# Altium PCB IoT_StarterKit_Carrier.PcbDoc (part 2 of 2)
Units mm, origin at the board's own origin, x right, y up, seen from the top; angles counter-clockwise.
Board outline 84.71 x 84.24 mm, 4 copper layers (Top, PWR, MID, Bottom), stack 1.612 mm thick; 101 components, 113 nets, 468 pads, 142 vias.
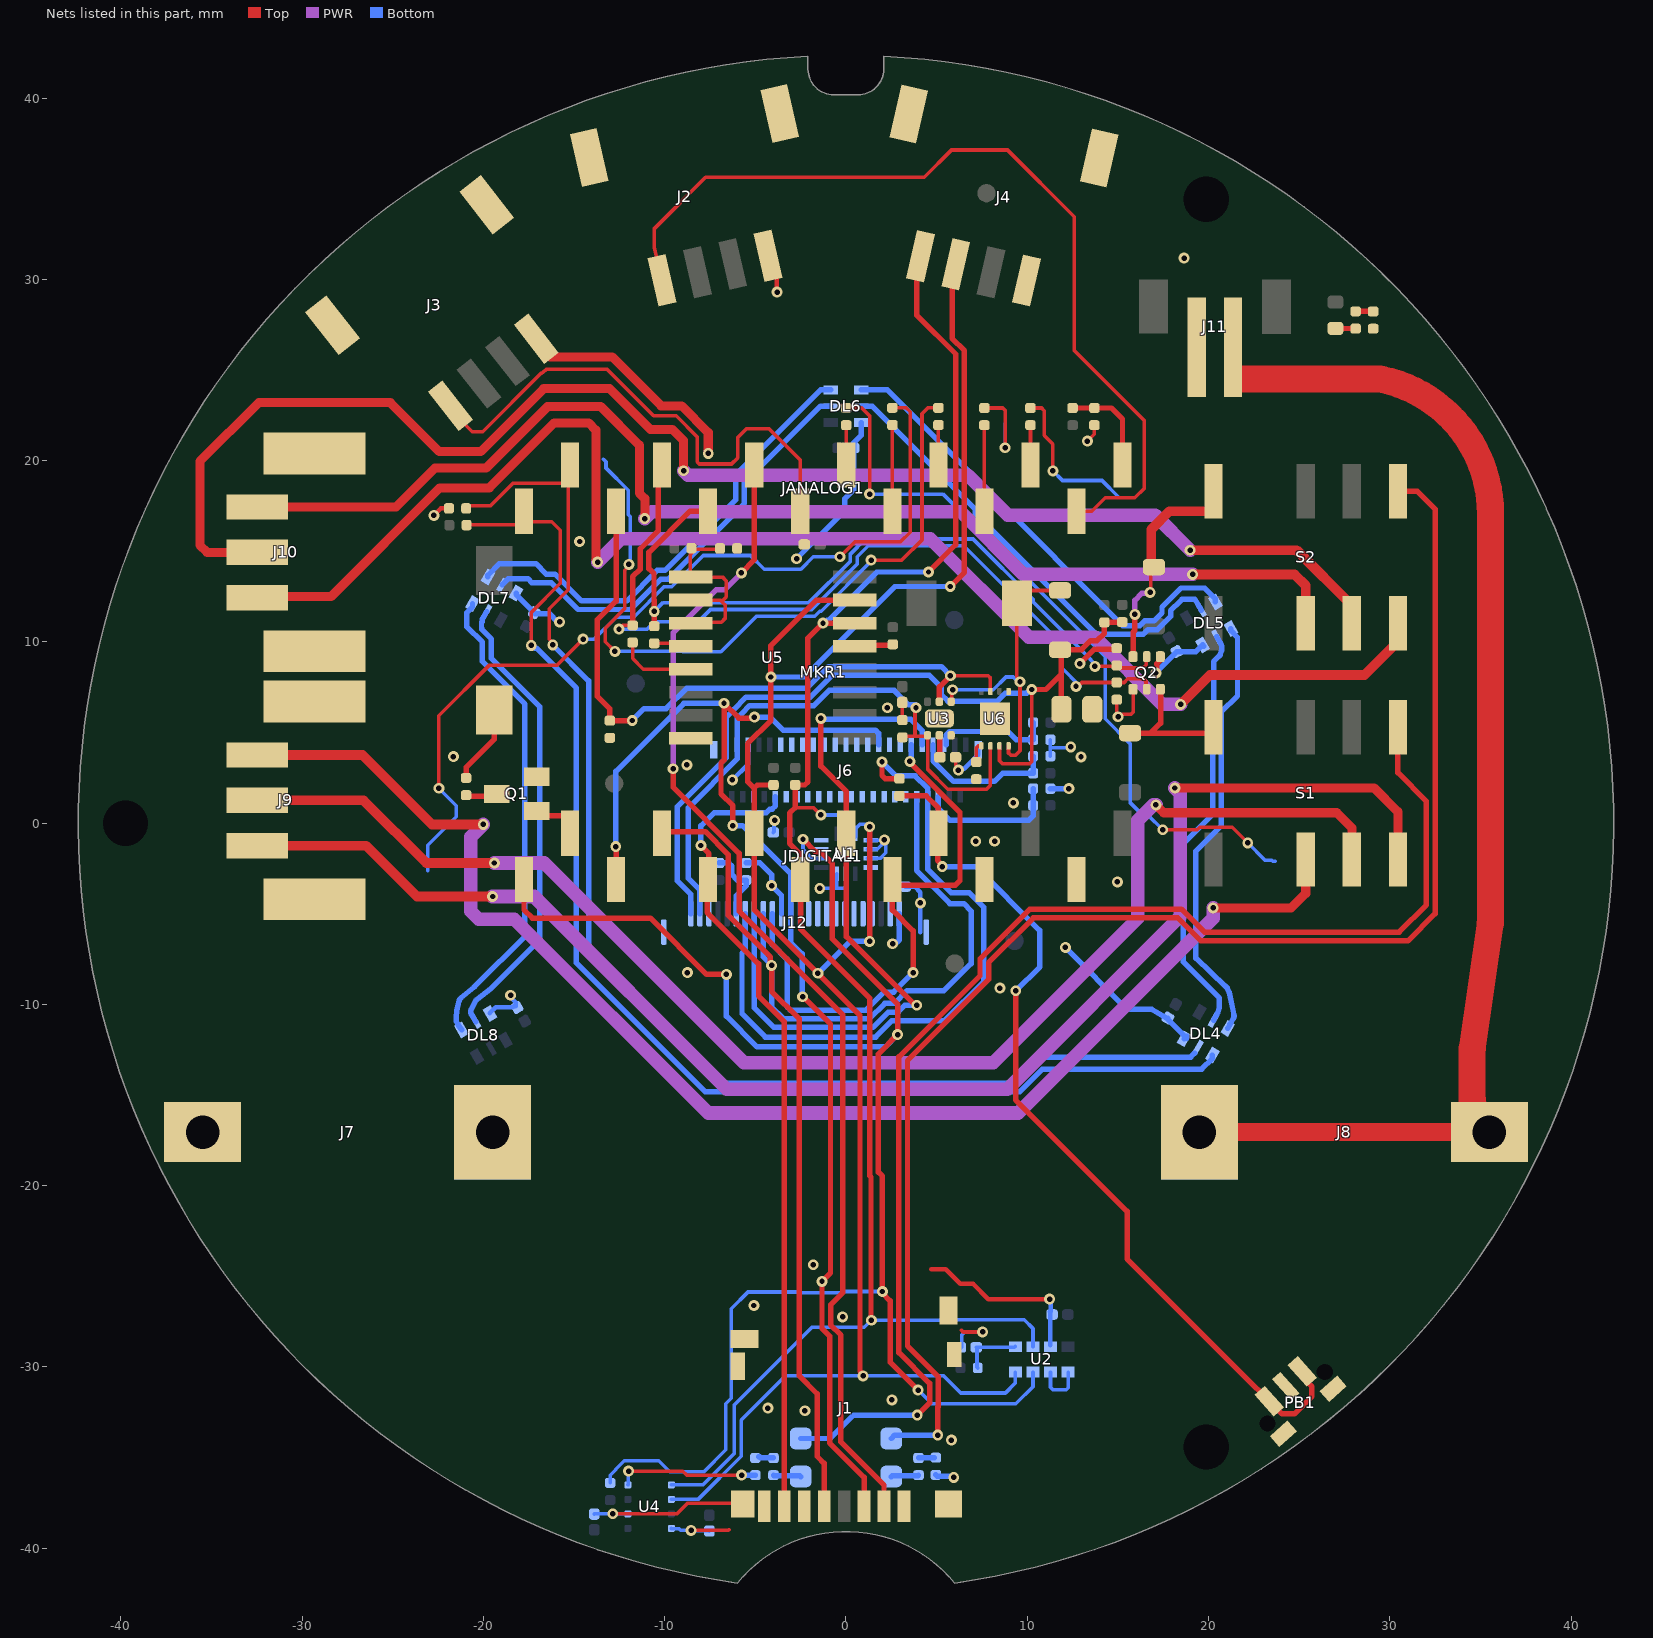
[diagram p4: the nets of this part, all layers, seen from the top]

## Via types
v1: diameter 0.6, hole 0.3, Top to Bottom, tented both sides, 142 vias

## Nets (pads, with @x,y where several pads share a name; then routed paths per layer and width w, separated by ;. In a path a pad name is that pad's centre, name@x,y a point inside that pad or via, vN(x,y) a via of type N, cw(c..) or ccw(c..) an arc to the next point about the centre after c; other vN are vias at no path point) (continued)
BACKLIGHT: JANALOG1.12 MKR1.3 R19.2 U3.5 U6.3 | length 37.2
  Top w0.2: v1(5.761,8.128) 7.843,8.128 7.968,8.003 U6.3@7.968,7.261
  Top w0.3: JANALOG1.12@-12.684,17.211 -12.684,12.247 -13.713,11.219 -13.713,6.992 -13.027,6.307 R19.2@-13.027,5.655 -13.024,5.657 -11.795,5.657 v1(-11.793,5.66) v1@-11.809,5.676 ; U3.5@5.15,6.693 5.15,7.517 v1(5.761,8.128)
  Bottom w0.3: v1(-11.793,5.66) -11.144,6.309 -9.918,6.309 -8.795,7.432 -2.166,7.432 -0.967,8.631 5.257,8.631 v1(5.761,8.128)
BUZZER_1: JDIGITAL1.2 MKR1.7 Q1.1 | length 2.7
  Top w0.3: Q1.1@-17.061,0.659 -16.816,0.415 -15.574,0.415 -15.224,0.065 JDIGITAL1.2@-15.224,-0.569
CS: J6.37 J12.17 JDIGITAL1.8 MKR1.13 | length 39.8
  Top w0.3: v1(-1.388,5.78) -1.388,3.139 0.016,1.735 JDIGITAL1.8@0.016,-0.569 0.016,-6.265 3.8,-10.049 v1(3.9,-10.049)
  Bottom w0.3: J12.17@-5.06,-5 -5.06,-10.189 -3.978,-11.271 1.489,-11.271 2.336,-10.424 2.877,-10.424 3.251,-10.049 v1(3.9,-10.049) ; v1(-1.388,5.78) -1.344,5.736 2.543,5.736 2.544,5.737 3.561,5.737 4.2,5.098 J6.37@4.2,4.325
DB0_5: J6.28
DB1_5: J12.11
DB01_5: J6.27
DB2_5: J12.10
DB02_5: J6.26
DB3_5: J12.9
DB03_5: J6.25
DB4_5: J12.8
DB04_5: J6.24
DB5_5: J12.7
DB05_5: J6.23
DB6_5: J12.6
DB06_5: J6.22
DB7_5: J12.5
DB07_5: J6.21
DB08_5: J6.20
DB09_5: J6.19
DB10_5: J6.18
DB11_5: J6.17
DB12_5: J6.16
DB13_5: J6.15
DB14_5: J6.14
DB15_5: J6.13
DB16_5: J6.12
DB17_5: J6.11
DE_5: J6.31
DIN(SDA): J1.3 J6.29 J12.13 JDIGITAL1.3 MKR1.8 | length 71.7
  Top w0.3: v1(-12.7,-1.3) -12.684,-1.316 JDIGITAL1.3@-12.684,-3.109 ; v1(-6.729,6.609) v1@-6.724,6.603 ; v1(-6.244,-0.137) -6.244,0.967 -6.895,1.618 -6.895,3.316 -6.724,3.487 v1@-6.724,6.603 ; v1(-5.054,5.845) -5.111,5.788 -5.909,5.788 v1@-6.724,6.603 ; v1(-2.394,-9.579) -2.37,-9.579 -0.855,-11.094 -0.855,-24.817 v1(-1.325,-25.287) -1.325,-27.887 -0.906,-28.306 -0.906,-34.193 0.998,-36.097 J1.3@0.998,-37.694
  Bottom w0.3: v1(-12.7,-1.3) -12.7,2.851 -8.942,6.609 v1(-6.729,6.609) ; v1(-6.244,-0.137) -5.712,-0.137 -3.06,-2.789 J12.13@-3.06,-5 -3.06,-6.577 -2.422,-7.215 -2.422,-9.551 v1(-2.394,-9.579) ; v1(-5.054,5.845) -4.194,5.845 -3.473,5.124 1.624,5.124 1.8,4.949 J6.29@1.8,4.325
DISP_DC_1: J6.35 J12.15 JDIGITAL1.9 MKR1.14 | length 31.5
  Top w0.3: JDIGITAL1.9@2.556,-3.109 JDIGITAL1.9@2.556,-3.437 ; v1(3.523,3.401) 3.523,3.354 6.291,0.586 6.291,-3.171 6.025,-3.437 JDIGITAL1.9@2.556,-3.437 ; v1(3.7,-8.249) 3.7,-5.949 2.556,-4.805 JDIGITAL1.9@2.556,-3.437
  Bottom w0.3: J12.15@-4.06,-5 -4.06,-6.702 -3.244,-7.518 -3.244,-10.14 -3.068,-10.316 1.093,-10.316 2.087,-9.321 2.628,-9.321 v1(3.7,-8.249) ; v1(3.523,3.401) 3.523,3.483 3.6,3.56 J6.35@3.6,4.325
DISP_RST_1: J6.38 J12.18 R9.1 | length 38.2
  Top w0.3: v1(1.987,3.374) 1.987,2.626 2.162,2.45 R9.1@2.95,2.45
  Bottom w0.3: J12.18@-5.56,-5 -5.56,-6.998 -5.738,-7.177 -5.738,-10.511 -4.445,-11.804 1.632,-11.804 2.534,-10.902 5.447,-10.902 7.6,-8.749 7.6,-4.649 6.8,-3.849 5.808,-3.849 4.5,-2.541 4.5,1.925 3.815,2.61 2.75,2.61 v1(1.987,3.374)
GND: C1.1 C2.1 C3.1 C4.1 C5.1 C6.1 C7.1 C8.1 C9.1 C10.1 C11.1 C12.1 C13.1 C14.2 C15.1 DL4.4 DL5.4 DL6.4 DL7.4 DL8.4 J1.6 J1.CD2 J1.SH1 J1.SH2 J1.SH3 J1.SH4 J2.4 J2.SS1 J2.SS2 J3.4 J3.SS1 J3.SS2 J4.4 J4.SS1 J4.SS2 J6.5 J6.6 J6.MP1 J6.MP2 J7.1 J7.2 J9.MP1 J9.MP2 J10.MP1 J10.MP2 J11.1 J12.1 J12.2 J12.14 J12.22 J12.MP1 J12.MP2 JDIGITAL1.11 MKR1.GND pad.H10 pad.H11 PB1.2 PB1.MNT Q1.2 Q2.1 Q2.4 R4.2 R5.2 R13.1 R14.1 R15.1 R19.1 R21.1 R24.1 R25.1 R26.1 R27.1 R29.1 R32.1 R40.1 R41.1 U1.1 U1.2 U1.3 U1.6 U1.7 U2.6 U3.3 U3.7 U4.1 U4.5 U4.7 U5.8 U6.1 U6.9 | length 111.5
  Top w0.2: v1(-12.87,-38.102) -9.323,-38.102 -8.734,-37.514 -5.754,-37.514 J1.SH1@-5.702,-37.566 ; v1(-11.993,-35.752) -9.008,-35.752 -8.79,-35.97 v1(-5.757,-35.97) ; v1(-8.543,-39.017) -6.489,-39.017 -6.457,-38.986 ; C6.1@3.107,6.656 3.112,6.652 3.112,5.686 R21.1@3.116,5.682 ; C7.1@6.043,3.631 6.049,3.625 6.049,3.186 6.201,3.033 v1(6.201,2.925) ; 6.373,-27.987 6.46,-28.074 v1(7.537,-28.074) ; v1(13.316,21.071) 13.7,21.456 R32.1@13.7,21.951 ; v1@14.937,6.01 R5.2@14.937,6.809 ; v1(15.009,5.868) 15.009,6.01 15.075,5.945 15.194,5.945 15.248,5.999 15.722,5.999 15.839,6.116 Q2.4@15.839,7.381
  Top w0.25: v1(-22.733,16.973) -22.348,17.359 R29.1@-21.905,17.359 ; J2.4@-4.297,31.296 -3.826,30.824 -3.826,29.319 v1(-3.802,29.295) ; 4.692,-24.618 5.511,-24.618 6.312,-25.419 7.01,-25.419 7.855,-26.264 v1(11.231,-26.264)
  Top w0.3: JDIGITAL1.11@7.636,-3.109 7.553,-3.025 JDIGITAL1.11@7.7,-2.878 ; v1(12.908,8.799) 13.692,9.583 R4.2@14.937,9.583 ; v1(17.097,8.281) 17.154,8.339 17.154,8.803 Q2.1@17.339,8.988
  Top w0.5: J3.4@-17.094,26.718 -17.094,26.49 -16.32,25.717 -12.901,25.717 -10.201,23.017 -9.074,23.017 -7.6,21.543 v1(-7.6,20.4)
  Bottom w0.2: C1.1@-13.886,-38.119 -13.878,-38.111 -12.879,-38.111 v1(-12.87,-38.102) -12.865,-38.108 -12.036,-38.108 U4.7@-12.03,-38.113 ; U4.5@-12.03,-36.513 -12.012,-36.494 -12.012,-35.771 v1(-11.993,-35.752) ; U4.1@-9.63,-38.913 -9.61,-38.933 -9.21,-38.933 -9.126,-39.017 v1(-8.543,-39.017) -8.524,-39.037 -7.557,-39.037 C2.1@-7.538,-39.056 ; C15.1@-4.011,-0.516 -3.974,-0.48 -3.974,0.111 v1(-3.938,0.147) ; v1(-1.451,-3.6) -0.5,-3.6 ; U1.7@-0.5,-2.8 -0.5,-3.6 ; U1.6@0,-2.8 0,-3.483 -0.117,-3.6 -0.5,-3.6 ; U1.3@1.175,-1.95 U1.3@1.375,-1.95 1.891,-1.95 2.2,-1.641 2.2,-1.004 v1(2.12,-0.924) 2.107,-0.937 1.188,-0.937 U1.1@1.175,-0.95 ; U1.2@1.175,-1.45 U1.2@1.375,-1.45 1.726,-1.45 v1@2.12,-1.057 ; C9.1@6.315,-28.966 6.395,-28.886 6.395,-28.228 6.55,-28.074 v1(7.537,-28.074) ; R13.1@11.275,3.695 11.275,4.135 ; R15.1@11.275,4.6 11.275,4.135 ; v1(12.4,4.2) 12.36,4.16 11.3,4.16 11.275,4.135
  Bottom w0.25: DL8.4@-19.646,-10.478 -19.327,-10.159 -18.38,-10.159 -18.319,-10.098 -18.226,-10.098 -18.226,-9.897 -18.5,-9.624 v1(-18.5,-9.5) v1@-18.641,-9.5 ; v1(-6.268,2.38) -5.4,3.248 J6.5@-5.4,4.325 ; v1(6.201,2.925) 6.268,2.992 6.517,2.992 7.3,3.775 J6.MP2@7.3,4.05 ; v1(11.231,-26.264) 11.298,-26.331 11.298,-26.947 11.277,-26.968 11.231,-26.968 11.273,-27.011 U2.6@11.273,-28.809
  Bottom w0.254: C4.1@3.27,-3.5 3.781,-3.5 4.1,-3.819 v1(4.1,-4.4) 4.1,-6.016
  Bottom w0.3: DL7.4@-18.196,12.686 -18.196,12.62 -17.201,11.625 C12.1@-17.201,11.605 -17.153,11.557 -16.367,11.557 -15.91,11.1 v1(-15.8,11.1) ; v1(-5.757,-35.97) -5.754,-35.972 -5.003,-35.972 R26.1@-5,-35.975 ; R24.1@-5.5,-2.199 -4.75,-2.199 -4.1,-2.849 v1(-4.1,-3.449) -3.56,-3.989 J12.14@-3.56,-5 ; v1(-2.726,14.583) -0.058,17.251 -0.058,17.908 0.432,18.399 C11.1@0.432,20.694 0.432,20.987 0.845,21.4 0.845,22.095 DL6.4@0.85,22.1 ; v1@2.805,-6.578 2.94,-6.443 J12.1@2.94,-5 ; R27.1@4.958,-35.958 5.026,-36.026 5.874,-36.026 v1(5.942,-36.095) ; R14.1@11.275,1.9 v1(12.3,1.9) ; v1(12.102,-6.861) 15.514,-10.273 16.856,-10.273 17.693,-10.756 C8.1@17.763,-10.756 ; v1(17.097,8.281) 17.097,8.303 18.252,9.458 C10.1@18.252,9.467 18.264,9.455 19.299,9.455 DL5.4@19.674,9.829 DL5.4@19.749,9.754 ; C8.1@17.763,-10.827 DL4.4@18.742,-11.807 ; DL4.4@18.651,-11.897 DL4.4@18.742,-11.807 ; DL4.4@18.742,-11.807 18.796,-11.86 18.796,-11.753 DL4.4@18.742,-11.807
  other v1: 5.818,-34.038 -2.267,-32.421 -4.306,-32.274 2.529,-31.818 -0.19,-27.241 -5.079,-26.614 -1.804,-24.367 8.491,-9.108 -8.75,-8.25 2.573,-6.654 14.968,-3.245 7.159,-1 8.2,-1 9.231,1.115 -8.775,3.212 12.966,3.653 -21.658,3.664 2.283,6.364 -14.692,15.535 18.653,31.166
GROVE_AN0_1: J2.1 JANALOG1.2 MKR1.A0 | length 51.1
  Top w0.2: J2.1@-10.143,29.946 -10.433,31.183 -10.569,31.773 -10.569,32.805 -7.747,35.628 4.317,35.628 5.821,37.131 8.914,37.131 12.59,33.455 12.59,26.075 16.464,22.201 16.464,18.479 15.936,17.951 14.3,17.951 13.56,17.211 JANALOG1.2@12.716,17.211 ; JANALOG1.2@12.716,16.461 JANALOG1.2@12.716,17.211 ; JANALOG1.2@12.716,17.374 JANALOG1.2@12.716,17.211
GROVE_AN6_1: J3.1 JANALOG1.8 MKR1.A6 | length 29.4
  Top w0.203: J3.1@-21.822,23.024 -21.822,22.793 -20.625,21.595 -20.04,21.595 -16.822,24.813 -16.564,25.001 -16.51,25.04 -13.187,25.04 -10.614,22.467 -9.367,22.467 -8.2,21.3 -8.2,19.928 -8.081,19.809 -6.317,19.809 -5.978,20.148 -5.978,21.274 -5.493,21.759 -4.251,21.759 -2.524,20.032 JANALOG1.8@-2.524,17.211
HSYNC_5: J6.32
IM0_5: J6.39 R10.1 R13.2 | length 8
  Bottom w0.3: J6.39@4.8,4.325 4.8,3.439 5.941,2.297 8.186,2.297 8.637,2.749 R10.1@10.325,2.749 R13.2@10.325,3.695
IM1_5: J6.40 R11.1 R14.2 | length 7.7
  Bottom w0.3: J6.40@5.1,1.45 5.1,0.8 5.749,0.151 10.08,0.151 10.325,0.396 R14.2@10.325,1.9
IM2_5: J6.41 R12.1 R15.2 | length 6.6
  Bottom w0.3: J6.41@5.522,4.325 5.522,4.861 5.714,5.053 8.933,5.053 9.386,4.6 R15.2@10.325,4.6 R12.1@10.325,5.547
INT_1: JDIGITAL1.1 MKR1.6 R16.1 U1.9 U2.2 | length 95.5
  Top w0.3: JDIGITAL1.1@-17.764,-3.109 -17.764,-4.785 -17.3,-5.249 -10.788,-5.249 -7.688,-8.349 v1(-6.6,-8.349) ; v1(-2.371,-0.89) -1.674,-1.587 -1.389,-1.587 -0.77,-2.206 -0.77,-6.379 2.862,-10.011 2.862,-10.259 2.85,-10.271 v1(2.85,-11.669) 1.781,-12.739 1.781,-19.253 2.008,-19.48 2.008,-25.924 2.437,-26.354 2.437,-29.735 v1(3.981,-31.279)
  Bottom w0.2: R16.1@-13.013,-36.4 -13.013,-35.985 -12.705,-35.677 -12.705,-35.647 -12.233,-35.174 -10.337,-35.174 -9.731,-35.78 -7.835,-35.78 -6.633,-34.578 -6.633,-32.038 -6.328,-31.733 -6.328,-26.79 -5.407,-25.869 -2.491,-25.869 -2.442,-25.918 -0.117,-25.918 -0.042,-25.843 v1(2.008,-25.843) ; v1(-2.371,-0.89) -2.371,-1.454 -1.875,-1.95 U1.9@-1.375,-1.95 U1.9@-1.175,-1.95 ; v1(3.981,-31.279) 4.743,-32.041 9.365,-32.041 10.315,-31.091 U2.2@10.315,-30.288
  Bottom w0.3: v1(-6.6,-8.349) -6.6,-10.649 -4.9,-12.349 2.171,-12.349 v1(2.85,-11.669)
LEDA_5: C5.2 D3.C J6.1 J12.24 R20.1 R22.2 U6.7 | length 47.6
  Top w0.2: U6.7@8.468,4.261 8.468,3.431 8.616,3.283 10.132,3.283 10.249,3.4 v1(10.249,7.369)
  Top w0.3: v1(10.249,7.369) 11.031,7.369 11.873,8.211 ; C5.2@11.873,6.279 11.873,8.211 ; R22.2@15.241,11.091 15.235,11.084 14.266,11.084 R20.1@14.259,11.078 14.259,10.473 13.847,10.061 13.494,10.061 12.997,9.564 D3.C@11.808,9.564 11.873,9.499 11.873,8.211
  Bottom w0.3: J12.24@-8.56,-5 -8.56,-3.928 -9.3,-3.188 -9.3,0.911 -6.6,3.611 J6.1@-6.6,4.325 -6.6,5.85 -6.217,6.233 -6.217,6.246 -5.509,6.954 -1.968,6.954 -0.769,8.154 4.597,8.154 5.254,7.497 5.254,7.097 5.621,6.729 8.355,6.729 8.793,7.168 9.966,7.168 10.168,7.369 v1(10.249,7.369)
LEDCKI_1: DL4.5 JANALOG1.13 MKR1.4 R29.2 | length 72.5
  Top w0.2: R29.2@-20.988,17.51 -19.61,17.51 -18.38,18.739 -15.624,18.739 -15.27,19.094 -15.27,19.706 JANALOG1.13@-15.224,19.751 -15.323,19.653 -15.323,12.878 -16.378,11.823 -16.378,10.137 -16.178,9.938 v1(-16.178,9.829)
  Bottom w0.3: v1(-16.178,9.829) -14.2,7.851 -14.2,-7.249 -7.1,-14.349 9.01,-14.349 10.443,-12.915 19.016,-12.915 DL4.5@19.235,-12.696
LEDK_5: J6.3 J12.23 R21.2 U3.1 U6.6 | length 34.1
  Top w0.2: R21.2@3.116,4.732 3.171,4.788 3.808,4.788 ; v1(3.861,6.36) 3.808,6.307 3.808,4.788 ; U6.6@7.968,4.261 7.968,2.081 7.754,1.868 5.615,1.868 4.5,2.982 U3.1@4.5,4.843 4.445,4.788 3.808,4.788
  Bottom w0.3: J12.23@-8.06,-5 -8.06,-3.689 -8.701,-3.048 -8.701,0.835 -6,3.536 J6.3@-6,4.325 -6,5.774 -5.739,6.035 -5.739,6.048 -5.311,6.476 -1.771,6.476 -0.929,7.318 2.66,7.318 3.453,6.525 v1@3.84,6.525
LEDSDI_1: DL4.6 JANALOG1.14 MKR1.5 R30.2 | length 70.4
  Top w0.2: R30.2@-20.986,16.469 -18.143,16.469 JANALOG1.14@-17.764,16.848 ; JANALOG1.14@-17.764,16.99 -17.764,16.976 -17.7,16.912 -17.414,16.626 -16.233,16.626 -15.76,16.154 -15.76,13.23 -17.368,11.622 v1(-17.368,9.808)
  Bottom w0.3: v1(-17.368,9.808) -17.286,9.808 -17.136,9.658 -17.084,9.658 -14.878,7.451 -14.878,-7.707 -7.758,-14.827 9.577,-14.827 10.832,-13.571 19.625,-13.571 20.21,-12.986 DL4.6@20.21,-12.797
MISO_1: J1.7 J6.10 JDIGITAL1.5 MKR1.10 | length 44.6
  Top w0.3: v1(-8.005,-1.237) -7.564,-1.678 -7.564,-3.068 -7.662,-3.166 -7.662,-4.926 -4.825,-7.763 -4.825,-9.538 -3.402,-10.96 J1.7@-3.402,-37.694
  Bottom w0.3: v1(-8.005,-1.237) -8.005,-0.156 -7.268,0.581 -4.392,0.581 -4.198,0.775 -4.076,0.775 -3.9,0.95 J6.10@-3.9,1.45
NetC7_2: C7.2 U3.2 | length 1.2
  Top w0.3: U3.2@5.15,4.843 5.162,4.832 5.162,3.642 C7.2@5.173,3.631
NetC9_2: C9.2 R28.1 U2.8 | length 3.4
  Bottom w0.2: R28.1@7.269,-30.059 7.227,-30.017 7.227,-28.966 C9.2@7.185,-28.924 9.288,-28.924 9.334,-28.878 U2.8@9.345,-28.888
NetD1_A: D1.A Q2.6 S1.12 | length 7.5
  Top w0.3: D1.A@15.674,4.965 16.799,4.965 ; Q2.6@17.408,7.381 17.408,7.436 17.353,7.381 17.353,5.518 16.799,4.965 ; S1.12@20.284,5.29 19.959,4.965 16.799,4.965
NetD2_A: D2.A Q2.3 S2.12 | length 12.5
  Top w0.2: v1(16.778,12.726) 16.809,12.757 16.809,13.982 D2.A@16.841,14.013
  Top w0.3: Q2.3@15.839,9.181 15.839,10.534 15.938,10.633 v1(15.938,11.513)
  Top w0.54: D2.A@16.841,14.013 16.839,14.015 16.839,16.194 17.853,17.208 20.054,17.208 20.284,17.438 S2.12@20.284,18.315
  PWR w0.3: v1@15.915,11.536 15.938,11.56 15.938,12.292 16.314,12.668 16.72,12.668 v1(16.778,12.726)
  Bottom w0.3: v1@15.915,11.536 v1(15.938,11.513)
NetD3_A: D3.A L6.2 U3.4 U6.8 | length 16.9
  Top w0.2: U3.4@5.8,6.693 5.841,6.734 5.841,7.316 v1(5.881,7.357) ; U6.8@8.968,4.261 8.968,3.869 9.085,3.752 9.365,3.752 9.598,3.986 9.598,6.201 v1(9.598,7.795) 9.598,7.904 9.425,8.077 L6.2@9.425,12.121 10.137,12.834 D3.A@11.808,12.834
  Bottom w0.2: v1(5.881,7.357) 8.126,7.357 8.826,8.057 9.228,8.057 9.49,7.795 v1(9.598,7.795)
NetDL1_C: DL1.C R3.2 | length 1.1
  Top w0.3: DL1.C@27,27.293 27.009,27.284 27.01,27.285 28.111,27.285 R3.2@28.118,27.278
NetDL2_A: DL2.A S1.8 | length 72.3
  Top w0.3: v1(3.931,-32.658) 4.609,-31.98 4.609,-30.908 2.915,-29.214 2.915,-12.898 7.391,-8.422 7.391,-7.496 10.14,-4.747 18.509,-4.747 19.776,-6.015 30.521,-6.015 32.021,-4.515 32.021,1.204 30.444,2.78 S1.8@30.444,5.29
  Bottom w0.3: DL2.A@-2.5,-33.95 -0.879,-33.95 0.413,-32.658 v1(3.931,-32.658)
NetDL2_C: DL2.C R6.2 | length 1.5
  Bottom w0.3: R6.2@-4,-35.975 -3.962,-36.013 -2.538,-36.013 DL2.C@-2.5,-36.05
NetDL3_A: DL3.A S2.8 | length 82.9
  Top w0.3: v1(5.058,-33.762) 5.058,-32.237 5.087,-32.208 5.087,-30.535 3.393,-28.841 3.393,-13.096 7.869,-8.62 7.869,-7.694 10.338,-5.225 18.311,-5.225 19.578,-6.493 30.999,-6.493 32.499,-4.992 32.499,17.328 31.512,18.315 S2.8@30.444,18.315
  Bottom w0.3: DL3.A@2.5,-33.95 2.687,-33.763 5.057,-33.763 v1(5.058,-33.762)
NetDL3_C: DL3.C R7.2 | length 1.5
  Bottom w0.3: DL3.C@2.5,-36.05 2.538,-36.013 3.962,-36.013 R7.2@4,-35.975
NetDL4_2: DL4.2 DL5.5 | length 23
  Bottom w0.3: DL4.2@20.281,-10.875 20.496,-10.491 ccw(c20.234,-10.344) 20.523,-10.425 20.589,-10.189 ccw(c20.3,-10.108) 20.6,-10.108 20.6,-9.649 18.6,-7.649 18.6,-1.149 20.222,0.473 20.222,6.314 20.286,6.378 20.286,8.907 20.617,9.238 20.639,9.298 20.711,9.488 ccw(c20.431,9.595) 20.73,9.611 ; DL5.5@20.453,10.279 20.683,9.88 20.683,9.879 cw(c20.423,9.731) 20.722,9.748 20.73,9.612
NetDL5_2: DL5.2 DL6.5 | length 25.4
  Bottom w0.3: DL6.5@0.85,23 1.443,23 7.14,17.304 7.14,17.084 13.817,10.407 16.396,10.407 16.665,10.675 17.186,10.675 17.911,11.401 17.911,11.72 18.456,12.265 18.543,12.352 18.665,12.353 19.245,12.359 DL5.2@19.603,11.751
NetDL6_2: DL6.2 DL7.5 | length 24.3
  Bottom w0.3: DL7.5@-18.975,13.136 -18.626,13.485 -17.555,13.485 -17.325,13.256 -16.254,13.256 -14.783,11.785 -11.893,11.785 -10.218,13.46 -9.786,13.46 -5.601,17.644 -5.601,18.799 -1.4,23 DL6.2@-0.85,23
NetDL7_2: DL7.2 DL8.5 | length 25.7
  Bottom w0.3: -20.431,-9.808 -20.67,-10.256 ccw(c-20.405,-10.397) -20.664,-10.549 DL8.5@-20.425,-10.955 ; -20.431,-9.807 cw(c-20.167,-9.949) -20.347,-9.709 -19.6,-9.149 -16.9,-6.449 -16.9,6.427 -19.562,9.089 -19.562,10.153 -20.094,10.685 -20.108,10.95 -20.108,11.071 -20.075,11.104 -20.075,11.149 -20.075,11.229 -20.035,11.298 DL7.2@-19.825,11.664
NetJ1_1: J1.1
NetJ1_8: J1.8
NetJ1_CD1: J1.CD1
NetJ12_19: J12.19 R23.1 R24.2 | length 4.2
  Bottom w0.3: R23.1@-7,-2.199 -6.476,-2.199 -6.3,-2.375 -6.3,-2.849 -6,-3.149 R24.2@-5.515,-3.149 -5.515,-3.464 -6.06,-4.009 J12.19@-6.06,-5
NetM1_2: M1.2 R8.2 | length 4.4
  Top w0.3: R8.2@-20.959,2.49 -20.959,3.077 -19.404,4.631 M1.2@-19.404,6.246
NetQ1_3: Q1.3 R8.1 | length 1.5
  Top w0.3: R8.1@-20.679,1.485 -19.385,1.485 Q1.3@-19.261,1.609
NetR3_1: R3.1 R25.2 | length 1
  Top w0.3: R3.1@28.118,28.228 28.12,28.226 29.081,28.226 R25.2@29.084,28.223
NetR6_1: R6.1 R26.2 | length 0.8
  Bottom w0.3: R26.2@-4.825,-34.97 -4.767,-34.97 -4.712,-35.025 R6.1@-4,-35.025
NetR7_1: R7.1 R27.2 | length 0.9
  Bottom w0.3: R7.1@4,-35.025 R27.2@4.88,-35.025
NetR17_1: R17.1 U5.4 | length 2.1
  Top w0.2: R17.1@-10.579,9.916 -8.728,9.916 U5.4@-8.575,9.763
NetR18_1: R18.1 U5.5 | length 4.3
  Top w0.2: R18.1@-11.77,9.962 -11.77,9.085 -11.178,8.493 U5.5@-8.575,8.493
NetR38_1: R38.1 U5.13 | length 2.2
  Top w0.3: U5.13@0.475,9.763 0.524,9.812 2.591,9.812 R38.1@2.639,9.86
NetR39_1: R39.1 R40.2 U5.1 U5.2 U5.3 | length 11.1
  Top w0.2: U5.1@-8.581,13.579 -8.589,13.587 -8.589,14.839 -8.582,14.839 -8.313,15.108 R40.2@-6.95,15.108 ; U5.3@-8.575,11.033 -8.52,11.088 -6.874,11.088 -6.652,11.31 -6.652,12.011 -6.798,12.157 ; U5.2@-8.575,12.303 -6.944,12.303 -6.798,12.157 ; U5.1@-8.575,13.573 -6.816,13.573 -6.601,13.357 -6.601,12.478 -6.798,12.281 -6.798,12.157
NetR41_2: R41.2 U6.5 | length 1.1
  Top w0.2: R41.2@7.19,3.37 7.19,4.144 7.307,4.261 U6.5@7.468,4.261
NetU1_4: U1.4
NetU1_10: U1.10
NetU1_11: U1.11
NetU2_3: U2.3 U2.4 | length 2.8
  Bottom w0.2: U2.3@11.285,-30.288 11.285,-31.129 11.418,-31.262 12.138,-31.262 12.255,-31.145 U2.4@12.255,-30.288
PA03_VREFA: JANALOG1.1 MKR1.AREF R31.1 R32.2 | length 5.6
  Top w0.3: R31.1@12.5,22.901 R32.2@13.715,22.901 ; R32.2@13.7,22.901 14.635,22.901 15.256,22.28 JANALOG1.1@15.256,19.751
PA04_AIN4: JANALOG1.5 MKR1.A3 R36.1 | length 2.2
  Top w0.2: JANALOG1.5@5.096,19.751 R36.1@5.096,21.961
PA05_AIN5: JANALOG1.6 MKR1.A4 R37.1 | length 4.7
  Top w0.2: JANALOG1.6@2.556,17.211 R37.1@2.556,21.961
PA06_AIN6: JANALOG1.7 MKR1.A5 R33.1 | length 3
  Top w0.2: JANALOG1.7@0.016,19.001 JANALOG1.7@0.016,19.751 R33.1@0.016,21.951
PA08_S0_I2C_SDA: J4.2 JDIGITAL1.6 MKR1.11 R2.1 U1.14 U2.1 U4.3 U5.15 | length 116.2
  Top w0.3: R2.1@-4,2.101 -4.888,2.101 -5.064,1.925 ; U5.15@0.475,12.303 -1.637,12.303 -4.144,9.795 v1(-4.144,8.06) -4.144,5.668 -5.428,4.384 -5.428,2.289 -5.064,1.925 ; v1(0.945,-30.499) 0.945,-30.418 0.772,-30.244 0.772,-10.605 v1(-1.55,-8.284) -5.064,-4.77 JDIGITAL1.6@-5.064,-0.569 -5.064,1.925 ; v1(1.301,-6.523) v1(1.301,-6.523) 1.303,-0.201 v1(1.305,-0.199) ; v1(5.753,13.053) 6.532,13.832 6.532,26.066 5.859,26.739 5.859,30.637 J4.2@6.054,30.832
  Bottom w0.2: U4.3@-9.63,-37.313 -8.164,-37.313 -5.784,-34.933 -5.784,-32.935 -3.348,-30.499 v1(0.945,-30.499) 5.385,-30.499 6.325,-31.438 8.795,-31.438 9.345,-30.888 U2.1@9.345,-30.288 ; U1.14@0.5,-0.775 0.525,-0.75 0.525,-0.3 0.751,-0.074 1.071,-0.074 1.197,-0.199 v1(1.305,-0.199)
  Bottom w0.3: v1(-4.144,8.06) -2.3,8.06 2.694,13.053 v1(5.753,13.053) ; v1(-1.55,-8.284) 0.212,-6.523 v1(1.301,-6.523)
PA09_S0_I2C_SCL: J4.1 JDIGITAL1.7 MKR1.12 R1.1 U1.13 U2.7 U4.4 U5.14 | length 99.7
  Top w0.2: -2.8,0.851 -2.798,0.853 -1.791,0.853 v1(-1.387,0.45)
  Top w0.3: U5.14@0.475,11.033 v1(-1.27,11.033) -2.1,10.203 -2.1,2.277 -2.276,2.101 R1.1@-2.8,2.101 -2.8,0.851 -3.105,0.546 -3.105,-1.119 -2.524,-1.7 JDIGITAL1.7@-2.524,-3.109 -2.5,-3.133 -2.5,-5.849 1.303,-9.652 1.303,-19.451 1.38,-19.528 1.38,-27.408 v1(1.399,-27.427) ; J4.1@4.105,31.282 3.911,31.087 3.911,28.012 6.055,25.868 6.055,15.356 v1(4.552,13.854)
  Bottom w0.2: U4.4@-9.63,-36.513 -7.899,-36.513 -6.162,-34.777 -6.162,-32.102 -1.879,-27.819 1.008,-27.819 v1(1.399,-27.427) 5.692,-27.427 5.719,-27.399 9.827,-27.399 10.315,-27.888 U2.7@10.315,-28.888 ; v1(-1.387,0.45) -0.28,0.45 0,0.17 U1.13@0,-0.775
  Bottom w0.3: v1(-1.27,11.033) -1.189,11.033 -1.039,11.183 -0.963,11.183 1.708,13.854 v1(4.552,13.854)
PA10_TCC0-W2: JANALOG1.11 MKR1.2 Q2.5 R5.1 R18.2 | length 46.7
  Top w0.2: v1(-12.524,10.698) -12.31,10.912 R18.2@-11.77,10.912 ; v1(12.689,7.541) 12.797,7.541 13.014,7.759 R5.1@14.937,7.759 15.347,7.759 15.547,7.959 16.403,7.959 16.552,7.81 16.552,7.418 Q2.5@16.589,7.381
  Top w0.3: R18.2@-11.77,10.912 -11.77,13.593 -11.35,14.014 -11.35,15.135 -10.35,16.134 -10.35,19.546 JANALOG1.11@-10.144,19.751
  Bottom w0.2: v1(-12.524,10.698) -10.979,10.698 -10.579,11.097 -8.165,11.097 -7.476,11.787 -1.886,11.787 0.622,14.295 0.622,14.693 1.224,15.296 6.495,15.296 11.903,9.887 11.903,8.563 12.91,7.556 12.674,7.556 v1(12.689,7.541)
PA17_S1_SCK: J1.5 J6.36 J12.16 JDIGITAL1.4 MKR1.9 | length 71.2
  Top w0.3: JDIGITAL1.4@-10.144,-0.569 -10.046,-0.47 -7.763,-0.47 -6.5,-1.733 -6.5,-5.073 -4.178,-7.396 -4.178,-7.771 v1(-4.1,-7.849) -4.1,-9.278 -2.591,-10.787 -2.591,-30.489 -1.586,-31.494 -1.586,-34.94 -1.202,-35.324 J1.5@-1.202,-37.694
  Bottom w0.3: J12.16@-4.56,-5 -4.56,-7.389 -4.041,-7.908 -4.1,-7.967 -4.1,-10.149 -3.456,-10.793 1.291,-10.793 2.138,-9.946 2.679,-9.946 3.376,-9.249 5.4,-9.249 6.9,-7.749 6.9,-4.849 6.5,-4.449 5.732,-4.449 3.9,-2.617 J6.36@3.9,1.45
PA22_TC4-W0: J1.2 JANALOG1.9 MKR1.0 | length 64.9
  Top w0.3: v1(-9.536,2.997) -9.536,1.979 -5.892,-1.666 -5.892,-4.857 -0.174,-10.575 -0.174,-25.905 -0.847,-26.578 -0.847,-27.689 -0.287,-28.249 -0.287,-34.136 2.098,-36.521 J1.2@2.098,-37.694 ; v1(-5.775,13.806) -5.064,14.517 JANALOG1.9@-5.064,19.751
  PWR w0.3: v1(-9.536,2.997) -9.536,10.5 -7.171,12.866 -6.715,12.866 v1(-5.775,13.806)
PA23_TC4-W1: JANALOG1.10 MKR1.1 Q2.2 R4.1 R17.2 | length 41.1
  Top w0.2: v1@13.761,8.649 R4.1@14.937,8.649 ; R4.1@14.937,8.697 15.081,8.553 16.387,8.553 16.563,8.729 16.563,9.155 Q2.2@16.589,9.181
  Top w0.3: R17.2@-10.579,10.866 v1(-10.581,11.675) ; v1(-10.581,11.675) -10.579,12.288 -10.593,12.301 -10.593,13.759 -10.872,14.038 -10.872,14.937 -8.597,17.211 JANALOG1.10@-7.604,17.211
  Bottom w0.2: v1(-10.581,11.675) -10.091,12.164 -2.043,12.164 0.244,14.451 0.244,14.85 1.068,15.673 7.008,15.673 10.332,12.349 10.332,12.192 13.486,9.038 13.486,9.004 13.732,8.757 v1(13.732,8.649)
PB02_AIN10: JANALOG1.3 MKR1.A1 R34.1 | length 2.2
  Top w0.2: JANALOG1.3@10.176,19.751 R34.1@10.176,21.951
PB03_AIN11: JANALOG1.4 MKR1.A2 R35.1 | length 4.7
  Top w0.2: JANALOG1.4@7.636,17.211 R35.1@7.636,21.951
PCLK_5: J6.30
RD_5: J6.34
RESET#: JDIGITAL1.10 MKR1.RST PB1.1 PB1.3 R9.2 | length 49.6
  Top w0.3: R9.2@2.95,1.5 4.427,1.5 5.096,0.832 5.096,-1.443 5.053,-1.486 5.053,-2.06 5.309,-2.316 v1(5.309,-2.397) ; v1(9.365,-9.253) 9.365,-15.277 15.506,-21.418 15.506,-24.047 22.004,-30.546 PB1.1@23.351,-31.892 24.053,-32.595 24.733,-32.595 25.701,-31.627 25.701,-31.093 25.171,-30.564 PB1.3@25.171,-30.253
  Bottom w0.3: v1(5.309,-2.397) 7.165,-2.397 10.689,-5.921 10.689,-6.188 10.691,-6.191 10.691,-7.926 v1(9.365,-9.253)
S1_3_3: J9.1 S1.3 | length 77
  Top w0.5: v1(20.253,-4.677) 20.269,-4.693 24.544,-4.693 25.364,-3.873 S1.3@25.364,-2.01
  Top w0.54: J9.1@-32.472,3.755 -26.677,3.755 -22.846,-0.076 v1(-20.009,-0.076)
  PWR w0.75: v1(-20.009,-0.076) -20.696,-0.762 -20.696,-4.861 -20.256,-5.3 -18.296,-5.3 -7.6,-15.996 9.508,-15.996 20.253,-5.251 v1(20.253,-4.677)
S1_4_3: J9.2 S1.4 | length 77.7
  Top w0.5: v1(17.1,1) 17.53,0.57 27.074,0.57 27.904,-0.26 S1.4@27.904,-2.01
  Top w0.54: J9.2@-32.472,1.255 -26.608,1.255 -23.153,-2.2 v1(-19.4,-2.2)
  PWR w0.75: v1(-19.4,-2.2) -16.644,-2.2 -5.626,-13.218 8.126,-13.218 16.098,-5.246 16.098,0.142 16.956,1 v1(17.1,1)
S1_5_3: J9.3 S1.5 | length 83.7
  Top w0.5: v1(18.145,1.936) 29.132,1.936 30.444,0.624 S1.5@30.444,-2.01
  Top w0.54: J9.3@-33.058,-1.245 -26.473,-1.245 -23.669,-4.049 v1(-19.5,-4.049)
  PWR w0.75: v1(-19.5,-4.049) -17.207,-4.049 -6.573,-14.683 8.903,-14.683 18.447,-5.14 18.447,1.635 v1(18.145,1.936)
S2_3_3: J10.1 S2.3 | length 68.8
  Top w0.5: J10.1@-32.472,17.435 -24.83,17.435 -22.677,19.588 -19.862,19.588 -16.466,22.983 -13.538,22.983 -11.4,20.845 -11.4,18.2 -11.1,17.9 v1(-11.1,16.8)
  Top w0.54: v1(19.119,13.719) 24.754,13.719 25.364,13.109 S2.3@25.364,11.015
  PWR w0.75: v1(-11.1,16.8) -10.726,17.174 6.326,17.174 9.781,13.719 v1(19.119,13.719)
S2_4_3: J10.2 S2.4 | length 82.3
  Top w0.5: J10.2@-32.472,14.935 -35.238,14.935 -35.642,15.339 -35.642,19.951 -32.392,23.2 -25.141,23.2 -22.431,20.49 -20.156,20.49 -16.673,23.973 -13.042,23.973 -10.791,21.721 -9.586,21.721 -8.962,21.097 v1(-8.962,19.439)
  Top w0.54: v1(18.987,15.051) 24.869,15.051 27.904,12.015 S2.4@27.904,11.015
  PWR w0.75: v1(-8.962,19.439) -8.715,19.192 6.725,19.192 8.927,16.991 17.047,16.991 v1(18.987,15.051)
S2_5_3: J10.3 S2.5 | length 81.8
  Top w0.5: J10.3@-33.191,12.5 -28.409,12.5 -22.413,18.495 -19.68,18.495 -16.094,22.082 -14.197,22.082 -13.8,21.685 -13.8,14.527 -13.7,14.427 v1(-13.7,14.4)
  Top w0.54: v1(18.458,6.549) 20.081,8.173 28.602,8.173 30.444,10.015 S2.5@30.444,11.015
  PWR w0.75: v1(-13.7,14.4) -12.407,15.693 4.651,15.693 10.091,10.253 13.746,10.253 17.45,6.549 v1(18.458,6.549)
SDO0_4: DL4.1 DL5.6 | length 24
  Bottom w0.3: DL4.1@21.06,-11.325 21.182,-11.107 21.369,-10.783 ccw(c21.109,-10.633) 21.403,-10.57 21.138,-9.326 21.032,-9.09 20.946,-9.004 19.3,-7.449 19.3,-1.549 20.7,-0.149 20.7,6.116 21.6,7.016 21.6,10.246 21.232,10.614 DL5.6@21.232,10.729
SDO1_4: DL5.1 DL6.6 | length 26.4
  Bottom w0.3: DL6.6@0.85,23.9 2.279,23.9 11.507,14.672 11.507,14.651 15.273,10.885 16.198,10.885 16.467,11.153 16.988,11.153 17.433,11.599 17.433,11.918 18.484,12.969 19.787,12.969 20.382,12.374 DL5.1@20.382,12.201
SDO2_4: DL6.1 DL7.6 | length 25.7
  Bottom w0.3: DL7.6@-19.754,13.586 -19.754,13.673 -19.119,14.309 -17.113,14.309 -16.538,13.734 -16.056,13.734 -14.585,12.263 -12.091,12.263 -10.416,13.938 -9.984,13.938 -6.079,17.842 -6.079,19.221 -1.4,23.9 DL6.1@-0.85,23.9
SDO3_4: DL7.1 DL8.6 | length 26.6
  Bottom w0.3: -21.348,-9.816 -21.47,-10.342 -21.499,-10.737 -21.499,-10.941 -21.35,-11.2 DL8.6@-21.204,-11.405 ; -21.347,-9.815 cw(c-21.056,-9.884) -21.247,-9.653 -20.508,-9.039 -20.4,-8.931 -17.718,-6.249 -17.718,6.569 -20.066,8.917 -20.066,9.981 -20.914,10.829 -20.914,11.617 -20.604,11.926 DL7.1@-20.604,12.114
TE_5: J12.4
TOUCH_Y0_4: R33.2 | length 40.6
  Top w0.2: R33.2@0.016,22.901 0.866,22.901 1.3,22.467 v1(1.3,18.151) v1@1.281,18.17 ; v1(17.472,-0.368) 19.373,-0.368 19.509,-0.232 21.303,-0.232 v1(22.161,-1.09)
  Bottom w0.2: v1(1.3,18.151) 5.347,18.151 14.31,9.188 14.31,5.75 15.674,4.387 15.674,1.137 16.388,0.423 16.681,0.423 v1(17.472,-0.368) ; v1(22.161,-1.09) 23.116,-2.046 23.479,-2.046 23.543,-2.11 23.687,-2.11
TOUCH_Y1_4: R34.2 | length 8.5
  Top w0.2: R34.2@10.176,22.901 10.786,22.901 10.931,22.756 10.931,21.388 11.41,20.909 v1(11.41,19.433)
  Bottom w0.2: v1(11.41,19.433) 11.943,18.9 14.125,18.9 15.027,17.998
TOUCH_Y2_4: R35.2 | length 4.6
  Top w0.2: R35.2@7.636,22.902 8.649,22.902 8.777,22.774 v1(8.777,20.708)
  Bottom w0.2: v1(8.777,20.708) 8.777,22.064
TOUCH_Y3_4: R36.2 | length 39.6
  Top w0.2: v1(-12.747,9.471) -13.285,10.009 -13.285,10.754 -12.198,11.841 -12.198,13.945 -11.977,14.166 v1(-11.977,14.274) ; v1(1.383,14.51) 3.082,14.51 4.196,15.624 4.196,22.582 4.525,22.911 R36.2@5.096,22.911
  Bottom w0.2: -13.384,20.077 -13.295,19.984 -13.24,19.926 -13.24,19.591 -12.008,18.359 -12.008,17.016 -11.901,16.909 -11.901,14.35 v1(-11.977,14.274) ; v1(-12.747,9.471) -9.02,9.471 -9,9.451 -6.9,9.451 -4.942,11.409 -1.73,11.409 -1.446,11.692 -1.372,11.692 1.383,14.447 v1(1.383,14.51)
TOUCH_Y4_4: R37.2 | length 48.1
  Top w0.2: v1(-22.464,1.925) -22.464,5.929 -19.694,8.699 -15.952,8.699 v1(-14.5,10.151) ; v1(-0.333,14.691) 0.487,15.511 2.999,15.511 3.538,16.05 3.538,22.687 3.313,22.911 R37.2@2.556,22.911
  Bottom w0.2: -23.073,-2.629 -23.073,-1.222 -21.5,0.351 -21.5,0.962 v1(-22.464,1.925) ; v1(-14.5,10.151) -13.888,10.151 -12.682,11.357 -11.716,11.357 -10.041,13.032 -9.609,13.032 -7.879,14.762 -5.266,14.762 -4.51,14.006 -2.487,14.006 -1.801,14.691 v1(-0.333,14.691)
VBAT_1: J8.1 J8.2 J11.2 pad.H8 pad.H9 | length 70.5
  Top w0.3: J11.2@21.353,26.25 21.353,24.856 21.703,24.506 21.894,24.506
  Top w1: J8.2@19.5,-17.049 J8.1@35.5,-17.049
  Top w1.5: 21.894,24.506 29.284,24.506 cw(c29.284,23.006) 29.605,24.472 cw(c27.97,17.062) 35.558,17.056 35.558,17.054 35.558,-5.325 cw(c34.058,-5.325) 35.543,-5.535 34.551,-12.44 ccw(c36.036,-12.651) 34.536,-12.648 34.536,-15.033 ccw(c37.076,-15.033) 35.28,-16.829 J8.1@35.5,-17.049
VIN: JDIGITAL1.13 MKR1.VIN
VSYNC_5: J6.33
pads on no net: DL8.1 DL8.2 FD1.1 FD2.1 FD3.1 FD4.1 FD5.1 FD6.1 J2.2 J3.2 J6.2 J6.4 J6.42 J6.43 J6.44 J6.45 J11.MP1 J11.MP2 J12.3 J12.12 PB1.NC1 PB1.NC2 S1.10 S2.10 U5.6 U5.7 U5.9 U5.10 U5.11 U5.12 U6.4

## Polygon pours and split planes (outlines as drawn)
TOUCH_Y0_4 on Bottom "poligonTest" (solid, pour order 134): 11.438,-19.954 21.397,-37.067 ccw(c0.299,-0.186) 42.709,-2.793 22.925,-1.86 cw(c0,0)
TOUCH_Y4_4 on Bottom "poligonTest" (solid, pour order 133): -22.971,-1.152 -42.785,-1.152 ccw(c-0.182,-0.104) -22.75,-36.253 -12.109,-19.554 cw(c0,0)
GND on Bottom "poligonTest" (hatched 90Degree grid 0.508 track 0.203, remove dead copper, pour order 137): -0.145,-16.414 cw(c-0.145,-0.342) -16.217,-0.342 cw(c-0.145,-0.342) -0.145,15.729 cw(c-0.145,-0.342) 15.927,-0.342 cw(c-0.145,-0.342)
TOUCH_Y3_4 on Bottom "poligonTest" (solid, pour order 132): -12.483,19.318 -22.369,36.489 ccw(c-0.195,0.118) -42.712,2.737 -22.925,1.86 cw(c0,0)
TOUCH_Y2_4 on Bottom "poligonTest" (solid, pour order 131): 10.488,20.469 20.346,37.655 ccw(c0.006,0.319) -18.981,38.361 -9.852,20.783 cw(c0,0)
TOUCH_Y1_4 on Bottom "poligonTest" (solid, pour order 130): 22.971,1.152 42.784,1.152 ccw(c0.212,0.117) 23.718,35.627 13.073,18.923 cw(c0,0)
+3V3 on MID "poligonTest" (hatched 90Degree grid 0.508 track 0.203, remove dead copper, pour order 142): -19.07,0.257 cw(c-0.087,0.257) -2.69,19.06 -2.822,-18.528 cw(c-0.087,0.257)
+5V on MID "poligonTest" (hatched 90Degree grid 0.508 track 0.203, pour order 141): -0.087,-18.726 cw(c-0.087,0.257) -2.492,-18.573 -2.359,19.103 cw(c-0.087,0.257) -0.087,19.239 cw(c-0.087,0.257) 18.896,0.257 cw(c-0.087,0.257)
+3V3 on MID "poligonTest" (solid, pour order 139): 10.739,-3.856 1.8,-12.795 1.8,-23.029 3.35,-24.579 6.696,-24.579 6.696,-37.557 -6.805,-37.557 -6.805,-24.579 -4.235,-24.579 -2.7,-23.044 -2.7,-3.794 -9.403,2.909 -9.403,10.597 -8.1,11.9 4.256,11.9 10.739,5.417
GND on PWR "C" (hatched 90Degree grid 0.508 track 0.203, remove dead copper, pour order 136): -1.653,42.768 ccw(c0,0) 1.653,42.768 1.653,41.569 cw(c0.653,41.569) 0.653,40.569 -0.653,40.569 cw(c-0.653,41.569) -1.653,41.569
GND on Top "C" (hatched 90Degree grid 0.508 track 0.203, remove dead copper, pour order 144): -1.653,42.768 ccw(c0,0) 1.653,42.768 1.653,41.569 cw(c0.653,41.569) 0.653,40.569 -0.653,40.569 cw(c-0.653,41.569) -1.653,41.569

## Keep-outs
Bottom:
  circle w5: c20.028,11.015 r0.5
  circle w5: c-20,-11.691 r0.5
  circle w5: c-19.4,12.4 r0.5
  circle w5: c20,-11.691 r0.5
  circle w5: c0,23 r0.5
Keep-Out Layer:
  circle w1: c-39.75,0 r2.2
  circle w1: c19.875,-34.425 r2.2
  circle w1: c19.875,34.425 r2.2
  region: -6.538,-32.769 -6.538,-27.519 -13.441,-27.519 -13.441,-32.769

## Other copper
Top:
  region net GND: 37.198,-12.179 38.699,-12.358 39.239,-11.947 40.673,-0.679 40.612,0.253 40.219,0.847 38.699,1.131 38.289,0.577 36.554,-11.338
Multi-Layer:
  pour cut-out: 11.494,-20.01 14.218,-24.864 21.293,-36.955 16.953,-41.925 6.672,-41.925 6.672,-24.506 7.22,-23.959 8.044,-23.461 8.641,-22.954
  pour cut-out: -12.109,-19.554 -15.172,-24.375 -22.723,-36.223 -17.064,-41.882 -6.444,-41.882 -6.444,-24.802 -7.331,-23.916 -8.155,-23.418 -8.752,-22.911

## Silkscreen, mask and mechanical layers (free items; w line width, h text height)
Top Overlay:
  drawing of 173 lines, arcs and shapes, not listed
Bottom Overlay:
  drawing of 87 lines, arcs and shapes, not listed
Top Solder:
  drawing of 9 lines, arcs and shapes, not listed
Bottom Solder:
  drawing of 5 lines, arcs and shapes, not listed
Top Designator:
  lines w0.013: -42.32,0.245 -42.28,-1.806 -42.141,-3.853 -41.903,-5.89 -41.567,-7.914 -41.133,-9.918 -40.602,-11.9 -39.976,-13.853 -39.256,-15.774 -38.443,-17.657 -37.541,-19.499 -36.55,-21.295 -35.473,-23.041 -34.313,-24.733 -33.072,-26.367 -31.754,-27.938 -30.361,-29.444 -28.896,-30.88 -27.364,-32.244 -25.767,-33.532 -24.11,-34.741 -22.396,-35.868 -20.63,-36.911 -18.815,-37.867 -16.956,-38.734 -15.057,-39.509 -13.123,-40.192 -11.158,-40.781 -9.167,-41.273 -7.154,-41.668 -5.124,-41.966 -3.083,-42.164 -1.034,-42.264 1.018,-42.264 3.066,-42.164 5.108,-41.966 7.138,-41.668 9.15,-41.273 11.142,-40.781 13.107,-40.192 15.041,-39.509 16.94,-38.734 18.799,-37.867 20.614,-36.911 22.38,-35.868 24.094,-34.741 25.751,-33.532 27.348,-32.244 28.88,-30.88 30.344,-29.444 31.738,-27.938 33.056,-26.367 34.297,-24.733 35.457,-23.041 36.534,-21.295 37.525,-19.499 38.427,-17.657 39.24,-15.774 39.96,-13.853 40.586,-11.9 41.117,-9.918 41.551,-7.914 41.887,-5.89 42.125,-3.853 42.264,-1.806 42.304,0.245 42.244,2.295 42.085,4.34 41.827,6.375 41.47,8.395 41.017,10.396 40.466,12.372 39.821,14.319 39.082,16.232 38.251,18.108 37.33,19.941 36.322,21.727 35.228,23.462 34.051,25.142 32.794,26.764 31.46,28.322 30.053,29.814 28.574,31.236 27.028,32.584 25.419,33.856 23.75,35.049 22.025,36.159 20.249,37.185 18.425,38.123 16.557,38.971 14.651,39.728 12.71,40.392 10.739,40.961 8.743,41.434 6.726,41.809 4.694,42.087 2.65,42.265 2.145,42.285 2.145,41.593 2.138,41.446 2.083,41.169 1.97,40.897 1.806,40.652 1.598,40.444 1.353,40.28 1.081,40.167 0.804,40.112 0.657,40.105 -0.673,40.105 -0.82,40.112 -1.097,40.167 -1.369,40.28 -1.614,40.444 -1.822,40.652 -1.986,40.897 -2.099,41.169 -2.154,41.446 -2.161,41.593 -2.161,42.285 -2.667,42.265 -4.71,42.087 -6.743,41.809 -8.759,41.434 -10.755,40.961 -12.726,40.392 -14.667,39.728 -16.573,38.971 -18.441,38.123 -20.265,37.185 -22.042,36.159 -23.766,35.049 -25.435,33.856 -27.045,32.584 -28.59,31.236 -30.069,29.814 -31.477,28.322 -32.81,26.764 -34.067,25.142 -35.244,23.462 -36.338,21.727 -37.346,19.941 -38.267,18.108 -39.098,16.232 -39.837,14.319 -40.483,12.372 -41.033,10.396 -41.487,8.395 -41.843,6.375 -42.101,4.34 -42.26,2.295 -42.32,0.245
Route Tool Path:
  drawing of 487 lines, arcs and shapes, not listed
Board:
  lines w0.1: -2.098,42.285 -2.098,41.594 -2.091,41.453 -2.038,41.187 -1.93,40.927 -1.773,40.692 -1.574,40.493 -1.339,40.336 -1.079,40.228 -0.813,40.175 -0.672,40.168 0.656,40.168 0.797,40.175 1.063,40.228 1.323,40.336 1.558,40.493 1.757,40.692 1.914,40.927 2.022,41.187 2.074,41.453 2.081,41.594 2.081,42.306 ; -2.099,42.305 ccw(c0,0) -5.992,-41.931 cw(c0,-46.8) 5.992,-41.931 ccw(c0,0) 2.082,42.306
Bottom Assembly (Mech10):
  circle w0.013: c-39.75,0 r1.25
  circle w0.013: c19.875,-34.425 r1.25
  circle w0.013: c19.875,34.425 r1.25
Top Assembly (Mech13):
  region: 0.665,1.025 1.168,0.361 2.911,2.201
  region: -2.911,-2.201 -0.665,-1.025 -1.168,-0.361
  lines w0.013: 11.983,-1.019 13.817,0.367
